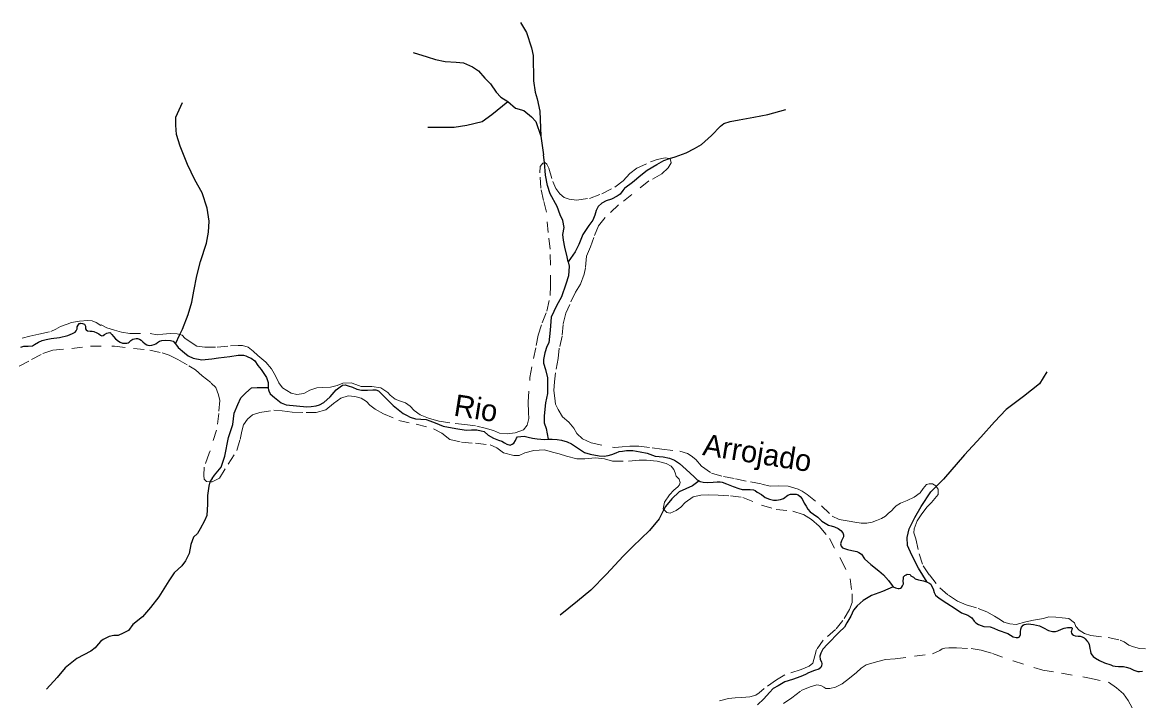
# Model space of a CAD drawing. Extents: x 391.8 to 446, y 8452 to 8507.5.
# Drawn here: x 426.58 to 436.93, y 8477.58 to 8483.85 of the extents above; entities that cross this region are included whole.
import ezdxf
from ezdxf.enums import TextEntityAlignment as Align

# ---------------------------------------------------------------- set-up
doc = ezdxf.new("R2010")
doc.units = 0
doc.header["$LTSCALE"] = 0.064
doc.linetypes.add('LONG_DASHED', pattern=[7.5, 6, -1.5])
doc.linetypes.add('SHORT_DASHED', pattern=[2.7, 1.5, -1.2])
for name, color, linetype, lineweight in [('21', 7, 'SHORT_DASHED', 13), ('7', 7, 'Continuous', 25), ('9', 7, 'LONG_DASHED', 25)]:
    doc.layers.add(name, color=color, linetype=linetype, lineweight=lineweight)
doc.layers.add('61', color=7, linetype='Continuous')

msp = doc.modelspace()

# ---------------------------------------------------------------- linework, layer by layer
at = {"layer": '21'}
for points in [[(428.0411, 8480.9655), (428.0618, 8480.9603), (428.0886, 8480.9335), (428.1193, 8480.9105), (428.1998, 8480.8569), (428.2726, 8480.8493), (428.3876, 8480.8493), (428.5103, 8480.8608), (428.5811, 8480.8628), (428.6232, 8480.8628), (428.6731, 8480.8475), (428.7191, 8480.8131), (428.7651, 8480.771), (428.8379, 8480.7097), (428.8916, 8480.6484), (428.9261, 8480.5834), (428.9567, 8480.5183), (428.9912, 8480.4723), (429.0717, 8480.4226), (429.1254, 8480.4111), (429.1905, 8480.4188), (429.2442, 8480.4494), (429.3094, 8480.4723), (429.363, 8480.4762), (429.4359, 8480.48), (429.4972, 8480.4953), (429.5509, 8480.5145), (429.6275, 8480.5183), (429.6697, 8480.503), (429.7195, 8480.4838), (429.8192, 8480.4838), (429.9035, 8480.4723), (429.9687, 8480.4302), (429.9879, 8480.4034), (430.036, 8480.3674), (430.0743, 8480.3521), (430.1318, 8480.333), (430.174, 8480.3024), (430.2123, 8480.2641), (430.266, 8480.222), (430.3427, 8480.1913), (430.4423, 8480.1645), (430.5918, 8480.1416), (430.68, 8480.1339), (430.7912, 8480.1186), (430.8678, 8480.0995), (430.9445, 8480.0765), (431.002, 8480.0535), (431.071, 8480.0459), (431.1477, 8480.0574), (431.2243, 8480.0842), (431.2588, 8480.1263), (431.2742, 8480.1875), (431.2703, 8480.2449), (431.2665, 8480.3406), (431.2827, 8480.5688), (431.3172, 8480.7449), (431.3402, 8480.8636), (431.3594, 8480.9593), (431.3977, 8481.0742), (431.4399, 8481.1814), (431.4705, 8481.3268), (431.4743, 8481.4163), (431.4743, 8481.6077), (431.4705, 8481.757), (431.4513, 8481.9102), (431.436, 8482.0995), (431.4092, 8482.2067), (431.3824, 8482.3216), (431.3747, 8482.4632), (431.3785, 8482.5207), (431.4015, 8482.5513), (431.4165, 8482.5573)], [(431.4165, 8482.5573), (431.4207, 8482.5589), (431.4399, 8482.5436), (431.459, 8482.5053), (431.4935, 8482.3828), (431.5242, 8482.3178), (431.5587, 8482.268), (431.6009, 8482.2335), (431.6469, 8482.2182), (431.7159, 8482.2106), (431.8347, 8482.2259), (431.9497, 8482.268), (432.0685, 8482.3292), (432.1452, 8482.3867), (432.2065, 8482.4556), (432.2717, 8482.5053), (432.3982, 8482.5628), (432.4595, 8482.5857), (432.5362, 8482.6011), (432.5764, 8482.5944)], [(432.5764, 8482.5944), (432.5822, 8482.5934), (432.5899, 8482.5551), (432.563, 8482.5092), (432.5055, 8482.4517), (432.3829, 8482.3867), (432.103, 8482.1646), (431.9804, 8482.0498), (431.919, 8481.9732), (431.873, 8481.8622), (431.8424, 8481.778), (431.8079, 8481.6899), (431.7964, 8481.5827), (431.7849, 8481.5253), (431.7506, 8481.4306), (431.7046, 8481.3579), (431.6509, 8481.243), (431.6164, 8481.1626), (431.5896, 8481.0593), (431.5819, 8480.9521), (431.5551, 8480.841), (431.5436, 8480.7453), (431.5206, 8480.6113), (431.5091, 8480.5271), (431.5052, 8480.4467), (431.5128, 8480.3755), (431.5205, 8480.3219), (431.5435, 8480.2722), (431.5856, 8480.2033), (431.6431, 8480.1535), (431.6891, 8480.0999), (431.716, 8480.0501), (431.7696, 8480.0004), (431.8501, 8479.9621), (432.0686, 8479.92), (432.1376, 8479.9276), (432.2066, 8479.9315), (432.291, 8479.9315), (432.4136, 8479.9161), (432.5056, 8479.9047), (432.6705, 8479.8855), (432.7415, 8479.8652), (432.776, 8479.8422), (432.8182, 8479.8078), (432.8718, 8479.7465), (432.9638, 8479.6815), (433.075, 8479.6508), (433.1862, 8479.6317), (433.3242, 8479.6011), (433.4315, 8479.5819), (433.5082, 8479.5628), (433.5887, 8479.5666), (433.673, 8479.5628), (433.765, 8479.536), (433.8033, 8479.5168), (433.8493, 8479.4862), (433.9835, 8479.379), (434.0809, 8479.2854), (434.1461, 8479.2548), (434.2381, 8479.2394), (434.2918, 8479.228), (434.3493, 8479.2203), (434.4029, 8479.2203), (434.4528, 8479.228), (434.4911, 8479.2433), (434.5371, 8479.2624), (434.5754, 8479.2854), (434.6023, 8479.3122), (434.6291, 8479.3352), (434.6559, 8479.362), (434.6751, 8479.3811), (434.7134, 8479.4041), (434.7748, 8479.4309), (434.8399, 8479.4615), (434.8974, 8479.4998), (434.9243, 8479.5419), (434.9558, 8479.5775), (434.9788, 8479.5851), (435.0094, 8479.5851), (435.0401, 8479.566), (435.0451, 8479.5593)], [(426.5833, 8480.9322), (426.6523, 8480.9513), (426.7366, 8480.9705), (426.8478, 8480.9935), (426.8938, 8481.0164), (426.936, 8481.0394), (426.9973, 8481.0624), (427.0395, 8481.0777), (427.1123, 8481.0892), (427.189, 8481.0968), (427.2311, 8481.093), (427.2656, 8481.0777), (427.3116, 8481.0509), (427.3143, 8481.056), (427.3642, 8481.0292), (427.437, 8481.0062), (427.5022, 8480.9871), (427.5788, 8480.9756), (427.7666, 8480.9756), (427.8318, 8480.9641), (427.8855, 8480.968), (427.9506, 8480.9756), (428.0158, 8480.9718), (428.0411, 8480.9655)], [(426.5546, 8480.6715), (426.6687, 8480.7336), (426.7723, 8480.7906), (426.8656, 8480.8216), (427.0419, 8480.8372), (427.213, 8480.8579), (427.4359, 8480.8579), (427.6121, 8480.8372), (427.7624, 8480.8216), (427.8765, 8480.7957), (427.9439, 8480.775), (428.0216, 8480.7336), (428.1253, 8480.6767), (428.1875, 8480.6404), (428.2497, 8480.5835), (428.3327, 8480.5162), (428.3741, 8480.4748), (428.4, 8480.4075), (428.4104, 8480.3557), (428.4022, 8480.235), (428.3815, 8480.0797), (428.3141, 8479.8674), (428.2674, 8479.738), (428.2622, 8479.6603), (428.2675, 8479.6276), (428.2882, 8479.6069), (428.3208, 8479.6036)], [(428.3208, 8479.6036), (428.3401, 8479.6017), (428.4075, 8479.6379), (428.4904, 8479.7674), (428.5682, 8479.8916), (428.5993, 8479.9952), (428.6148, 8480.0728), (428.6304, 8480.1298), (428.6667, 8480.1815), (428.7133, 8480.2229), (428.7807, 8480.2437), (428.9103, 8480.2644), (428.9881, 8480.2592), (429.0814, 8480.2488), (429.211, 8480.2437), (429.3043, 8480.2437), (429.3924, 8480.2695), (429.465, 8480.3265), (429.5324, 8480.3783), (429.5997, 8480.399), (429.6619, 8480.3938), (429.719, 8480.3783), (429.7708, 8480.3472), (429.8019, 8480.311), (429.8486, 8480.2747), (429.9263, 8480.2333), (430.0684, 8480.1716), (430.2291, 8480.1353), (430.3898, 8480.0939), (430.4676, 8480.0525), (430.5401, 8479.9956), (430.649, 8479.9697), (430.7786, 8479.9593), (430.9134, 8479.9438), (430.9756, 8479.9179), (431.0378, 8479.8713), (431.1363, 8479.8454), (431.1829, 8479.8454), (431.2348, 8479.8713), (431.3177, 8479.892), (431.4189, 8479.8974), (431.4915, 8479.8767), (431.5537, 8479.8612), (431.6211, 8479.8405), (431.7196, 8479.8146), (431.7922, 8479.8146), (431.8907, 8479.8249), (431.9736, 8479.8146), (432.0462, 8479.7939), (432.1965, 8479.7939), (432.295, 8479.8042), (432.3624, 8479.8042), (432.4609, 8479.7939), (432.5438, 8479.7732), (432.5905, 8479.7473), (432.6164, 8479.7162), (432.6268, 8479.6851), (432.6371, 8479.6541), (432.6631, 8479.6282), (432.6734, 8479.5971), (432.6682, 8479.5764), (432.6527, 8479.5557), (432.6164, 8479.5247), (432.5749, 8479.4832)], [(435.0451, 8479.5593), (435.0631, 8479.5354), (435.0631, 8479.4856), (435.0324, 8479.4473), (435.0018, 8479.4129), (434.9596, 8479.3708), (434.9098, 8479.3057), (434.8676, 8479.2406), (434.8408, 8479.1679), (434.8369, 8479.1296), (434.8553, 8479.0738), (434.8859, 8478.936), (434.9243, 8478.825), (434.9818, 8478.7408), (435.0776, 8478.6221), (435.1581, 8478.5532), (435.2424, 8478.4996), (435.3229, 8478.4651), (435.4341, 8478.4307), (435.5146, 8478.4001), (435.5856, 8478.3604), (435.6392, 8478.326), (435.6699, 8478.303), (435.7274, 8478.2877), (435.7849, 8478.2839), (435.8731, 8478.3068), (435.9459, 8478.3222), (436.0379, 8478.3375), (436.0877, 8478.3528), (436.1529, 8478.349), (436.2104, 8478.3451), (436.2717, 8478.3375), (436.3254, 8478.2992), (436.3369, 8478.2647), (436.3676, 8478.2303), (436.4174, 8478.1997), (436.4749, 8478.1805), (436.6359, 8478.1614), (436.7471, 8478.1384), (436.7854, 8478.1231), (436.8276, 8478.0925), (436.8697, 8478.0772), (436.9272, 8478.0618), (436.9809, 8478.058)], [(432.5749, 8479.4832), (432.5283, 8479.4159), (432.5179, 8479.3538), (432.5237, 8479.3471)], [(432.6371, 8479.3383), (432.6786, 8479.3694), (432.7201, 8479.4108), (432.7927, 8479.4625), (432.8652, 8479.4781), (432.9326, 8479.4832), (433.0259, 8479.4781), (433.14, 8479.4729), (433.254, 8479.4574), (433.4279, 8479.388), (433.5627, 8479.3466), (433.7182, 8479.3311), (433.8167, 8479.3), (433.8893, 8479.2534), (433.9619, 8479.1913), (434.0552, 8479.0774), (434.164, 8478.8807), (434.247, 8478.7047), (434.2677, 8478.5649), (434.2677, 8478.4872), (434.2423, 8478.4223), (434.1801, 8478.3188), (434.1127, 8478.236), (433.9987, 8478.1376), (433.9365, 8478.0496), (433.9209, 8477.9926), (433.9033, 8477.9241), (433.867, 8477.8982), (433.7944, 8477.8671), (433.6441, 8477.8154), (433.5664, 8477.7688), (433.4523, 8477.6911), (433.4057, 8477.6497), (433.3746, 8477.629), (433.3175, 8477.6135), (433.245, 8477.6083), (433.1827, 8477.6031), (433.1205, 8477.5979), (433.0376, 8477.5772)], [(432.5237, 8479.3471), (432.549, 8479.3176), (432.5801, 8479.3124), (432.6371, 8479.3383)], [(433.6293, 8477.5517), (433.707, 8477.6035), (433.7952, 8477.6708), (433.8781, 8477.707), (433.9403, 8477.7225), (433.9766, 8477.7174), (434.0025, 8477.7018), (434.0233, 8477.6915), (434.0595, 8477.6915), (434.1114, 8477.7018), (434.1736, 8477.7329), (434.241, 8477.7847), (434.3075, 8477.8384), (434.3489, 8477.8771), (434.3963, 8477.9079), (434.4919, 8477.9377), (434.574, 8477.9582), (434.6653, 8477.965), (434.8423, 8477.989), (435.0102, 8478.0113), (435.0778, 8478.0421), (435.0997, 8478.0575), (435.1252, 8478.0643), (435.1617, 8478.0677), (435.2, 8478.066), (435.2328, 8478.0654), (435.3676, 8478.0602), (435.4609, 8478.0447), (435.5646, 8478.0136), (435.7564, 8477.9463), (436.0311, 8477.8583), (436.2042, 8477.832), (436.4634, 8477.7854), (436.6396, 8477.7491), (436.7122, 8477.6974), (436.7796, 8477.6404), (436.8211, 8477.5783), (436.8574, 8477.511)]]:
    msp.add_lwpolyline(points, dxfattribs=at)
at = {"layer": '7'}
for points in [[(431.6379, 8481.6395), (431.6287, 8481.6843), (431.6051, 8481.7729), (431.5932, 8481.8379), (431.5873, 8481.891), (431.5991, 8481.956), (431.5873, 8482.0209), (431.5637, 8482.0741), (431.5341, 8482.1509), (431.469, 8482.269), (431.4454, 8482.3458), (431.4277, 8482.4403), (431.4165, 8482.5573), (431.4097, 8482.6291)], [(432.1609, 8482.3221), (432.1425, 8482.2981), (432.1171, 8482.2632), (432.0916, 8482.2473), (432.0374, 8482.2186), (431.9897, 8482.2027), (431.9483, 8482.1805), (431.9133, 8482.1519), (431.8973, 8482.1137), (431.8846, 8482.0692), (431.8655, 8482.0247), (431.8273, 8481.9738), (431.7732, 8481.8911), (431.7349, 8481.7989), (431.7031, 8481.7321), (431.6379, 8481.6395)], [(431.6379, 8481.6395), (431.6464, 8481.5982), (431.6405, 8481.5096), (431.6168, 8481.4328), (431.5754, 8481.3147), (431.5281, 8481.232), (431.4808, 8481.1257), (431.469, 8481.0076), (431.4571, 8480.8895), (431.4394, 8480.8541), (431.4217, 8480.795), (431.4098, 8480.7359), (431.4098, 8480.7005), (431.4276, 8480.6414), (431.4453, 8480.5647), (431.4452, 8480.4924), (431.4452, 8480.4216), (431.4275, 8480.333), (431.4156, 8480.2149), (431.4156, 8480.1499), (431.4334, 8480.0968), (431.4514, 8479.9969)], [(426.57, 8480.8483), (426.5973, 8480.8574), (426.6383, 8480.8596), (426.6769, 8480.8619), (426.6974, 8480.8733), (426.7316, 8480.896), (426.768, 8480.9096), (426.8044, 8480.921), (426.8499, 8480.9278), (426.9281, 8480.9397), (427.0032, 8480.9556), (427.0487, 8480.9761), (427.0738, 8480.9875), (427.0829, 8480.9988), (427.0897, 8481.017), (427.0897, 8481.0375), (427.1011, 8481.0534), (427.1102, 8481.067), (427.1193, 8481.0693), (427.1261, 8481.0716), (427.1398, 8481.0693), (427.1603, 8481.0625), (427.1625, 8481.0556), (427.1671, 8481.0443), (427.1671, 8481.0284), (427.1694, 8481.017), (427.1739, 8481.0079), (427.1876, 8481.0011), (427.2103, 8480.9966), (427.2308, 8480.9966), (427.2467, 8480.9943), (427.2718, 8480.9829), (427.2922, 8480.9716), (427.3059, 8480.9602), (427.3196, 8480.9534), (427.3332, 8480.9556), (427.3446, 8480.9647), (427.3651, 8480.9784), (427.3787, 8480.9829), (427.3947, 8480.9852), (427.3992, 8480.9829), (427.4038, 8480.9761), (427.4129, 8480.9647), (427.4265, 8480.9466), (427.447, 8480.9261), (427.4743, 8480.9056), (427.4889, 8480.8966), (427.5117, 8480.8852), (427.5504, 8480.8852), (427.5617, 8480.8875), (427.5731, 8480.8966), (427.5891, 8480.9102), (427.6073, 8480.9238), (427.6368, 8480.9306), (427.6505, 8480.9306), (427.6687, 8480.9216), (427.6824, 8480.9125), (427.6983, 8480.8988), (427.721, 8480.8806), (427.737, 8480.8716)], [(427.737, 8480.8716), (427.7461, 8480.867), (427.7643, 8480.8647), (427.7825, 8480.867), (427.803, 8480.8738), (427.8189, 8480.8806), (427.8348, 8480.892)], [(427.8348, 8480.892), (427.853, 8480.9034), (427.8758, 8480.9102), (427.9122, 8480.9125), (427.9554, 8480.9102), (427.9791, 8480.903), (427.9951, 8480.8848), (428.0004, 8480.8783)], [(428.0004, 8480.8783), (428.0269, 8480.8462), (428.0838, 8480.7962), (428.1202, 8480.7689), (428.1657, 8480.7484), (428.2454, 8480.7325), (428.3364, 8480.7416), (428.4001, 8480.7507), (428.5048, 8480.7621), (428.5822, 8480.7757), (428.6323, 8480.7757), (428.6527, 8480.7689), (428.6778, 8480.7575), (428.7005, 8480.7484), (428.7369, 8480.7234), (428.763, 8480.6797), (428.7949, 8480.6411), (428.8427, 8480.5683), (428.8609, 8480.5229), (428.8609, 8480.477)], [(428.3404, 8479.6342), (428.3618, 8479.6646), (428.4246, 8479.7388), (428.4589, 8479.8415), (428.4931, 8480.0126), (428.5336, 8480.1347), (428.545, 8480.2374), (428.5793, 8480.3173), (428.6078, 8480.38), (428.6535, 8480.4257), (428.7049, 8480.4713), (428.7563, 8480.477), (428.8609, 8480.477)], [(428.8609, 8480.477), (428.8609, 8480.4706), (428.8632, 8480.4547), (428.8654, 8480.4433), (428.8768, 8480.4161), (428.9178, 8480.382), (428.9792, 8480.3343), (429.0247, 8480.3138), (429.1203, 8480.307), (429.2159, 8480.2979), (429.2569, 8480.3002), (429.3024, 8480.3047), (429.3342, 8480.3161), (429.3752, 8480.3365), (429.4344, 8480.3888), (429.489, 8480.4547), (429.5254, 8480.482), (429.5482, 8480.4979), (429.5732, 8480.5002), (429.6005, 8480.4911), (429.6415, 8480.4774), (429.6801, 8480.4615), (429.7234, 8480.4524), (429.7803, 8480.4524), (429.8272, 8480.454), (429.8568, 8480.454), (429.8796, 8480.4449), (429.8909, 8480.4358), (429.9273, 8480.3995), (430.0161, 8480.3086), (430.1094, 8480.2358), (430.139, 8480.2199), (430.1754, 8480.2017), (430.2232, 8480.1858), (430.2733, 8480.1836), (430.3211, 8480.179), (430.3552, 8480.1676), (430.4053, 8480.1495), (430.4781, 8480.1176), (430.5964, 8480.0972), (430.692, 8480.0813), (430.7434, 8480.0828), (430.7912, 8480.0828), (430.8299, 8480.076), (430.8595, 8480.0669), (430.8959, 8480.0351), (430.9459, 8480.0078), (430.9915, 8479.9897), (431.0233, 8479.9783), (431.0461, 8479.9647), (431.0688, 8479.951), (431.1007, 8479.9419), (431.1189, 8479.951), (431.1348, 8479.9601), (431.1508, 8479.9851), (431.1599, 8480.0056), (431.169, 8480.0192), (431.1985, 8480.0215), (431.2281, 8480.0238), (431.2668, 8480.0147), (431.3078, 8480.0078), (431.3493, 8480.0007), (431.4191, 8479.9952), (431.4514, 8479.9969)], [(431.4514, 8479.9969), (431.4888, 8479.9989), (431.5365, 8479.9952), (431.5751, 8479.9879), (431.6265, 8479.9714), (431.6668, 8479.9531), (431.788, 8479.8743), (431.8404, 8479.8574), (431.9248, 8479.8427), (431.9707, 8479.8409), (432.0074, 8479.8464), (432.0423, 8479.8555), (432.0808, 8479.8702), (432.1084, 8479.883), (432.1396, 8479.8867), (432.1781, 8479.8922), (432.2368, 8479.894), (432.3029, 8479.8794), (432.3671, 8479.8665), (432.4424, 8479.8409), (432.5158, 8479.8335), (432.5745, 8479.8225), (432.6222, 8479.8024), (432.6681, 8479.7731), (432.7281, 8479.7174), (432.8034, 8479.6478), (432.8309, 8479.6203), (432.8483, 8479.6116)], [(432.8483, 8479.6116), (432.8603, 8479.6056), (432.886, 8479.5983), (432.93, 8479.5964), (432.9796, 8479.5983), (433.0163, 8479.6038), (433.0438, 8479.6038), (433.064, 8479.6001), (433.1025, 8479.5836), (433.1631, 8479.558), (433.2182, 8479.5396), (433.2494, 8479.5323), (433.3209, 8479.5323), (433.3521, 8479.5286), (433.3686, 8479.5231), (433.387, 8479.5085), (433.4255, 8479.4846), (433.4604, 8479.4571), (433.5008, 8479.4407), (433.5375, 8479.4315), (433.5669, 8479.4315), (433.6017, 8479.4388), (433.6311, 8479.4498), (433.6715, 8479.4791), (433.6966, 8479.4882), (433.7315, 8479.49), (433.748, 8479.4882), (433.7663, 8479.4809), (433.7847, 8479.468), (433.803, 8479.446), (433.8214, 8479.4057), (433.8398, 8479.3782), (433.8563, 8479.3489), (433.8783, 8479.3251), (433.9077, 8479.3049), (433.948, 8479.2756), (433.9866, 8479.2389), (434.0159, 8479.2188), (434.0458, 8479.2027), (434.0734, 8479.1954), (434.1027, 8479.1862), (434.1376, 8479.1716), (434.1615, 8479.1532), (434.1798, 8479.1312), (434.1872, 8479.1111), (434.1872, 8479.0927), (434.178, 8479.0762), (434.167, 8479.0579), (434.1596, 8479.0304), (434.1633, 8479.0066), (434.1761, 8478.9919), (434.1963, 8478.9846), (434.2239, 8478.9773), (434.2642, 8478.9663), (434.3083, 8478.9589), (434.3285, 8478.9498), (434.3542, 8478.9333), (434.3817, 8478.8911), (434.4386, 8478.838), (434.512, 8478.7793), (434.5566, 8478.7434), (434.6025, 8478.6884), (434.6373, 8478.6444), (434.6473, 8478.6302)], [(434.9609, 8478.6742), (434.8803, 8478.8031), (434.8201, 8478.9233), (434.78, 8479.0134), (434.775, 8479.0885), (434.795, 8479.1686), (434.8452, 8479.2737), (434.9053, 8479.3738), (434.9955, 8479.509), (435.0451, 8479.5593), (435.1115, 8479.6265)], [(434.6473, 8478.6302), (434.6685, 8478.6226), (434.6911, 8478.6166), (434.7002, 8478.6166), (434.7153, 8478.6196), (434.7244, 8478.6257), (434.7334, 8478.6392), (434.7425, 8478.6588), (434.7383, 8478.6874), (434.7414, 8478.7078), (434.7429, 8478.7229), (434.7547, 8478.7353), (434.7648, 8478.7422), (434.775, 8478.7486), (434.8021, 8478.7439), (434.8102, 8478.7324), (434.8328, 8478.7189), (434.8498, 8478.7056), (434.8815, 8478.6966), (434.9268, 8478.686), (434.954, 8478.677), (434.9609, 8478.6742)], [(434.6473, 8478.6302), (434.5463, 8478.5876), (434.4467, 8478.5522), (434.3686, 8478.504), (434.3111, 8478.4554), (434.2801, 8478.4156), (434.2535, 8478.3604), (434.2181, 8478.2985), (434.1938, 8478.2587), (434.1451, 8478.2101), (434.0367, 8478.0996), (433.9946, 8478.0532), (433.9747, 8478.0178), (433.9681, 8477.9891), (433.9703, 8477.9582), (433.9814, 8477.9383), (433.9858, 8477.9184), (433.9836, 8477.8985), (433.9769, 8477.883), (433.9592, 8477.8698), (433.9172, 8477.8565), (433.8611, 8477.8355), (433.8346, 8477.8201), (433.7925, 8477.8024), (433.7129, 8477.7737), (433.6421, 8477.7516), (433.5801, 8477.7162), (433.5358, 8477.6897), (433.5018, 8477.6535), (433.4487, 8477.5938), (433.389, 8477.5386)], [(434.9609, 8478.6742), (434.9767, 8478.6679), (434.9955, 8478.655), (435.0047, 8478.6326), (435.0166, 8478.6128), (435.0242, 8478.5781), (435.0378, 8478.554), (435.0725, 8478.5253), (435.1435, 8478.48), (435.2206, 8478.4302), (435.2795, 8478.391), (435.3369, 8478.3684), (435.3747, 8478.3442), (435.3973, 8478.3141), (435.4109, 8478.2975), (435.4351, 8478.2824), (435.4593, 8478.2718), (435.4865, 8478.2643), (435.5439, 8478.2597), (435.5791, 8478.2497), (435.6184, 8478.2301), (435.7075, 8478.1984), (435.7574, 8478.1697), (435.7846, 8478.1622), (435.8042, 8478.1622), (435.8148, 8478.1697), (435.8239, 8478.1909), (435.8254, 8478.215), (435.8284, 8478.2407), (435.8329, 8478.2573), (435.848, 8478.2754), (435.8601, 8478.2814), (435.8949, 8478.2874), (435.9463, 8478.2829), (436.0006, 8478.2708), (436.0384, 8478.2512), (436.0852, 8478.2271), (436.12, 8478.218), (436.1502, 8478.2165), (436.1698, 8478.2241), (436.2031, 8478.2392), (436.2303, 8478.2482), (436.2599, 8478.2544), (436.2901, 8478.2559), (436.2992, 8478.2544), (436.3037, 8478.2468), (436.3037, 8478.2438), (436.3007, 8478.2347), (436.2962, 8478.2242), (436.2931, 8478.2136), (436.2962, 8478.2016), (436.3022, 8478.1925), (436.3143, 8478.1834), (436.3324, 8478.1789), (436.3596, 8478.1744), (436.3778, 8478.1729), (436.3944, 8478.1669), (436.414, 8478.1578), (436.4231, 8478.1503), (436.4382, 8478.1321), (436.4503, 8478.1186), (436.4608, 8478.0974), (436.4639, 8478.0824), (436.4669, 8478.0597), (436.4729, 8478.0356), (436.4775, 8478.013), (436.488, 8477.9979), (436.4971, 8477.9873), (436.5186, 8477.9713), (436.5549, 8477.9486), (436.6032, 8477.929), (436.6622, 8477.9079), (436.6788, 8477.9003), (436.7014, 8477.8958), (436.7317, 8477.8943), (436.7785, 8477.8943), (436.8042, 8477.8883), (436.8359, 8477.8777), (436.8752, 8477.8596), (436.9099, 8477.8475), (436.9265, 8477.846), (436.9537, 8477.8506)]]:
    msp.add_lwpolyline(points, dxfattribs=at)
at = {"layer": '9'}
msp.add_line((428.0004, 8480.8783), (428.0411, 8480.9655), dxfattribs=at)
for points in [[(431.1962, 8483.8547), (431.2501, 8483.7614), (431.2967, 8483.6185), (431.3144, 8483.5476), (431.3162, 8483.3141), (431.3304, 8483.21), (431.3499, 8483.146), (431.3736, 8483.0338), (431.3853, 8482.8018), (431.4097, 8482.6291)], [(430.2025, 8483.5758), (430.3326, 8483.5344), (430.4095, 8483.5108), (430.4982, 8483.4931), (430.5987, 8483.4872), (430.6691, 8483.48), (430.7518, 8483.4425), (430.8061, 8483.4071), (430.8648, 8483.3395), (430.9171, 8483.2853), (430.9713, 8483.2096), (431.0127, 8483.1623), (431.0777, 8483.121)], [(428.0411, 8480.9655), (428.0647, 8481.0161), (428.1187, 8481.1509), (428.1525, 8481.2655), (428.1727, 8481.3666), (428.1997, 8481.5082), (428.2335, 8481.643), (428.2874, 8481.8115), (428.3077, 8481.9126), (428.3144, 8482.0138), (428.2942, 8482.1351), (428.2469, 8482.2767), (428.1795, 8482.398), (428.112, 8482.5396), (428.0445, 8482.7081), (428.0107, 8482.8159), (428.004, 8482.9036), (428.004, 8482.9777), (428.0647, 8483.1126)], [(430.3385, 8482.8848), (430.581, 8482.8848), (430.6993, 8482.9025), (430.8412, 8482.9379), (430.9299, 8483.0029), (431.0777, 8483.121)], [(431.0777, 8483.121), (431.1487, 8483.062), (431.2256, 8483.0383), (431.2966, 8482.979), (431.338, 8482.9376), (431.3853, 8482.8018)], [(432.5764, 8482.5944), (432.6281, 8482.6116), (432.7287, 8482.6471), (432.8055, 8482.6884), (432.8706, 8482.7239), (432.9652, 8482.8065), (433.0478, 8482.8949), (433.0774, 8482.9185), (433.1365, 8482.9362), (433.2193, 8482.954), (433.3553, 8482.9776), (433.4854, 8483.0012), (433.651, 8483.0485)], [(432.1609, 8482.3221), (432.2319, 8482.3753), (432.3088, 8482.4403), (432.3679, 8482.4875), (432.4566, 8482.5407), (432.5217, 8482.5761), (432.5764, 8482.5944)], [(436.0701, 8480.6209), (435.9994, 8480.5105), (435.8534, 8480.3924), (435.693, 8480.2722), (435.5827, 8480.1571), (435.4574, 8480.0169), (435.307, 8479.8517), (435.1115, 8479.6265)], [(428.3208, 8479.6036), (428.3104, 8479.562), (428.2989, 8479.4764), (428.2986, 8479.395), (428.2929, 8479.2923), (428.27, 8479.241), (428.2309, 8479.1691), (428.2061, 8479.1255), (428.1695, 8479.0904), (428.1444, 8479.0242), (428.1273, 8478.9387), (428.093, 8478.8702), (428.0587, 8478.8246), (427.9902, 8478.7618), (427.9388, 8478.6877), (427.848, 8478.5373), (427.77, 8478.4391), (427.6958, 8478.3535), (427.6075, 8478.2827), (427.5654, 8478.2262), (427.5163, 8478.2031), (427.4692, 8478.182), (427.4303, 8478.1801), (427.3869, 8478.1707), (427.332, 8478.1436), (427.3077, 8478.125), (427.2705, 8478.0822), (427.259, 8478.0653), (427.219, 8478.0367), (427.0877, 8477.9683), (426.9792, 8477.8827), (426.9049, 8477.7915), (426.8078, 8477.6831)], [(428.3404, 8479.6342), (428.3218, 8479.6076), (428.3208, 8479.6036)], [(432.8483, 8479.6116), (432.7874, 8479.5668), (432.6657, 8479.5092), (432.5952, 8479.4452), (432.5375, 8479.3748), (432.5237, 8479.3471)], [(432.5237, 8479.3471), (432.4799, 8479.2596), (432.3901, 8479.1508), (432.2364, 8479.0036), (432.1467, 8478.914), (431.9929, 8478.7477), (431.8455, 8478.6005), (431.7237, 8478.4981), (431.5635, 8478.3701)]]:
    msp.add_lwpolyline(points, dxfattribs=at)

# ---------------------------------------------------------------- texts
at = {"layer": '61'}
msp.add_text('Rio                          Arrojado', height=0.2, rotation=350.987, dxfattribs=at).set_placement((432.221, 8479.9551), align=Align.CENTER)

doc.saveas('drawing.dxf')
